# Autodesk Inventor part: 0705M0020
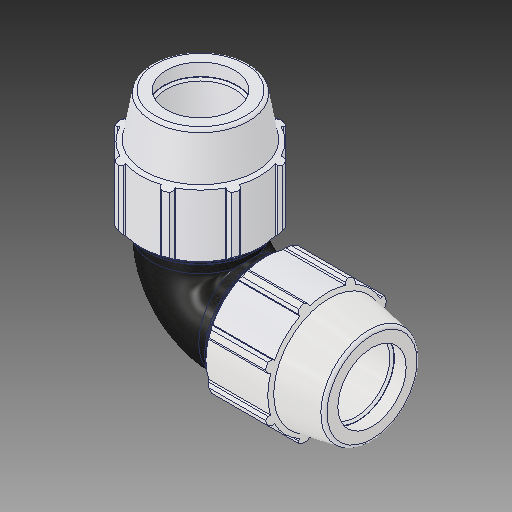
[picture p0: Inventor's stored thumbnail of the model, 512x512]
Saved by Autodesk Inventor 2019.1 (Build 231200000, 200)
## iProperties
Created: 2017-02
Part Number: 0705M0020
Material: PVC-Piping
Description: PLASSON 90° ELBOW 2'' - 2''
Document SubType Name: Modeling
Designer: KIM
Mass: 92.6774 g
Surface Area: 199.44 cm^2
Volume: 66.1981 cm^3
Density: 1.4 g/cm^3
Appearance: PTFE
Author: KIM
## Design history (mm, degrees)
derived "0705M0.ipt"
feature "Solid1::0705M0.ipt"
tag "TaggingFeature1"
body "Solid1"
other parameters: "d2" = 60.1, "d4" = 12.573, "d5" = 37.719, "d7" = 113.03, "d9" = 21.55371, "d11" = 3.7719, "d13" = 120 deg, "d14" = 84.14, "d15" = 10 deg, "d16" = 98.3361, "d18" = 3.005, "d19" = 35 deg, "d20" = 17.5 deg, "d21" = 105.1179, "d23" = 0, "d25" = 360 deg, "d27" = 2.2606, "d33" = 1.202, "d42" = 55.82412, "d43" = 3.3909, "d46" = 1.803, "d51" = 150.876, "d59" = 90 deg, "d63" = 109.982, "d64" = 54.09, "d67" = 84.7725, "d68" = 1.88595, "d70" = 90 deg, "d_" = 60.1, "E_" = 113.03, "A_" = 150.876, "l_" = 109.982
